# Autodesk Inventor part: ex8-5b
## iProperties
Author: Administrator
Created: 2001-03
Part Number: ex8-5b
Document SubType Name: Modeling
Designer: Administrator
Control State: 0
Master: False
Checked Out: False
PropertySet Name: Design Tracking Control
Shininess: 20.0
PropertySet Name: _Private Model Information
Density: 0.0
Volumn: 0.0
Area: 0.0
PropertySet Name: Model Information
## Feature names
1. Extrusion1
2. Hole1
